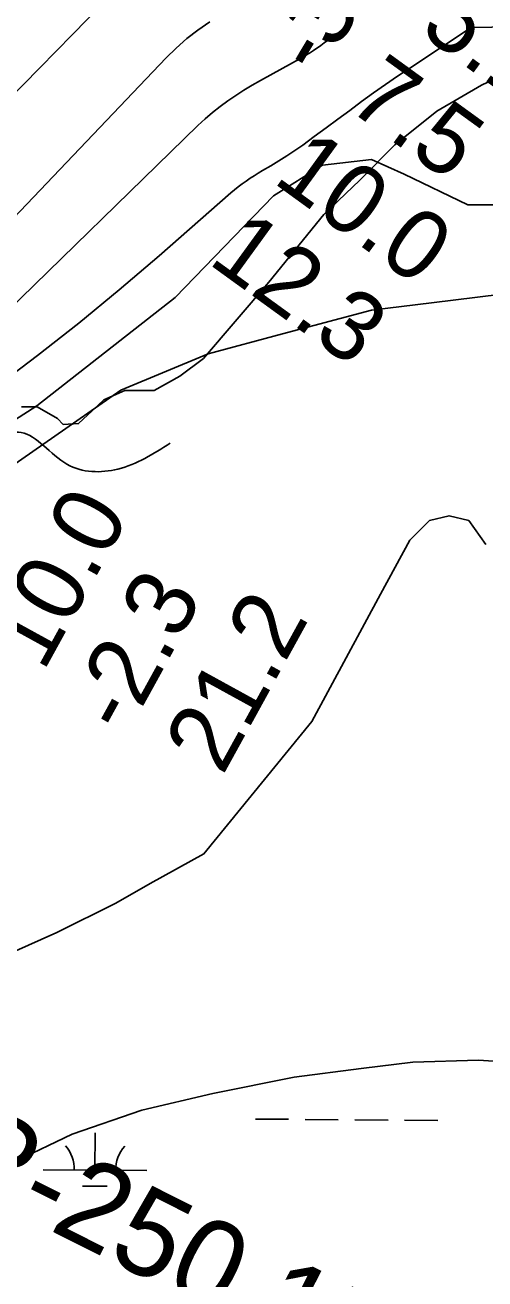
# Model space of a CAD drawing. Extents: x 3271442 to 3309282, y 752266 to 777610.
# Drawn here: x 3291666 to 3292110, y 763821 to 765032 of the extents above; entities that cross this region are included whole.
import ezdxf

# ---------------------------------------------------------------- set-up
doc = ezdxf.new("R2010")
doc.units = 0
for name, color, linetype in [('V-RIVR-EDGE', 7, 'Continuous'), ('V-RIVR-RANG', 7, 'Continuous'), ('V-RIVR-RANG-IDEN', 7, 'Continuous'), ('V-RRAP-FSHR', 7, 'Continuous'), ('V-SITE-VEGE', 7, 'Continuous'), ('V-TOPO-DPTH', 7, 'Continuous'), ('V-TOPO-MINR', 7, 'Continuous'), ('V-TOPO-WATR', 7, 'Continuous'), ('V-WETL-SWMP', 7, 'Continuous')]:
    doc.layers.add(name, color=color, linetype=linetype)

msp = doc.modelspace()

# ---------------------------------------------------------------- linework, layer by layer
at = {"layer": 'V-RIVR-EDGE'}
msp.add_lwpolyline([(3291662.3, 764663.8), (3291677.5, 764663.7), (3291697.1, 764652.4), (3291702.7, 764646.7), (3291717.5, 764647.5), (3291730.5, 764659.7), (3291741.9, 764670.5), (3291762.3, 764679.6), (3291790.6, 764679.5), (3291815.4, 764693.4), (3291838, 764710.3), (3291901.2, 764784), (3291954.4, 764849.5), (3291988.9, 764882.5), (3292022.8, 764916.7), (3292063.4, 764949.2), (3292106.4, 764974.3), (3292150.8, 764995.5)], dxfattribs=at)
at = {"layer": 'V-RRAP-FSHR'}
msp.add_spline([(3289175.3, 762139.2), (3289199.4, 762153.4), (3289238.8, 762167.3), (3289290.8, 762181.4), (3289361.3, 762211.5), (3289422.7, 762245.6), (3289515.6, 762307.8), (3289579.9, 762382.2), (3289624.8, 762451.5), (3289672.3, 762536.1), (3289709.2, 762613.4), (3289742.7, 762696.1), (3289778.2, 762754.9), (3289819.5, 762799.1), (3289911.4, 762921.9), (3289994.1, 763031.2), (3290081.2, 763125.2), (3290188.8, 763225.8), (3290291.4, 763333.1), (3290344.5, 763399.5), (3290388.7, 763467.2), (3290474.1, 763575.3), (3290571, 763693.2), (3290669.8, 763810.1), (3290775.6, 763894), (3290904.1, 763991.9), (3291011.4, 764077.3), (3291099.8, 764130.4), (3291153.6, 764153.5), (3291210.5, 764195.8), (3291300.7, 764249), (3291400.5, 764351.4), (3291483.3, 764483.3), (3291547.7, 764562.3), (3291620.8, 764622.9), (3291662, 764638.8), (3291706.2, 764608.3), (3291755.4, 764603.5), (3291805.9, 764628.5)], degree=3, dxfattribs=at)
at = {"layer": 'V-SITE-VEGE'}
msp.add_lwpolyline([(3290953.5, 763810.1), (3290991.4, 763829), (3291038.7, 763866.9), (3291100.2, 763904.8), (3291199.6, 763956.9), (3291351.1, 764013.7), (3291460, 764061.1), (3291516.8, 764080.1), (3291578.3, 764099), (3291654, 764136.9), (3291696.6, 764155.9), (3291753.4, 764184.3), (3291786.6, 764203.2), (3291838.6, 764231.7), (3291942.8, 764359.6), (3292009, 764482.7), (3292037.4, 764534.8), (3292056.4, 764553.8), (3292075.3, 764558.5), (3292094.2, 764553.8), (3292110.6, 764530.6)], dxfattribs=at)
at = {"layer": 'V-TOPO-DPTH'}
for points in [[(3291487.6, 764670.9), (3291802, 765000.7), (3291811.8, 765010.3), (3291822, 765019.4), (3291832.8, 765027.7), (3291844.1, 765035.5)], [(3291844.1, 765035.5), (3291832.8, 765027.7), (3291822, 765019.4), (3291811.8, 765010.3), (3291802, 765000.7), (3291487.6, 764670.9)], [(3291637.4, 764682.8), (3291677.8, 764713.3), (3291717.8, 764744.4), (3291756.8, 764776.7), (3291795.4, 764809.6), (3291864.5, 764870.3), (3291868.1, 764873.3), (3291871.7, 764876.3), (3291875.5, 764879.1), (3291879.2, 764881.8), (3291883.1, 764884.5), (3291887, 764887), (3291891, 764889.5), (3291895, 764891.9), (3291903, 764896.4), (3291910.9, 764901.2), (3291918.7, 764906.1), (3291926.4, 764911.3), (3291933.9, 764916.6), (3291945.1, 764924.9), (3291956.5, 764933.3), (3291967.9, 764941.7), (3291979.3, 764950.1), (3291990.8, 764958.6), (3292002.2, 764966.9), (3292013.8, 764975.1), (3292025.5, 764983.1), (3292037.2, 764991), (3292096.4, 765030.1), (3292196.8, 765031.7)], [(3291637.4, 764682.8), (3291677.8, 764713.3), (3291717.8, 764744.4), (3291756.8, 764776.7), (3291795.4, 764809.6), (3291864.5, 764870.3), (3291868.1, 764873.3), (3291871.7, 764876.3), (3291875.5, 764879.1), (3291879.2, 764881.8), (3291883.1, 764884.5), (3291887, 764887), (3291891, 764889.5), (3291895, 764891.9), (3291903, 764896.4), (3291910.9, 764901.2), (3291918.7, 764906.1), (3291926.4, 764911.3), (3291933.9, 764916.6), (3291945.1, 764924.9), (3291956.5, 764933.3), (3291967.9, 764941.7), (3291979.3, 764950.1), (3291990.8, 764958.6), (3292002.2, 764966.9), (3292013.8, 764975.1), (3292025.5, 764983.1), (3292037.2, 764991), (3292096.4, 765030.1), (3292196.8, 765031.7)], [(3292170.4, 764778), (3292058.2, 764764), (3292000.3, 764757), (3291914.4, 764734.2), (3291842.5, 764714.9), (3291758.3, 764679.8), (3291652.2, 764605.7)]]:
    msp.add_lwpolyline(points, dxfattribs=at)
at = {"layer": 'V-TOPO-MINR'}
msp.add_line((3291562.9, 764591.7), (3291677.3, 764664.5), dxfattribs=at)
for points in [[(3291648.4, 764958.8), (3291680.1, 764991.1), (3291711.8, 765023.5), (3291781.3, 765095)], [(3291487.6, 764670.9), (3291802, 765000.7), (3291811.8, 765010.3), (3291822, 765019.4), (3291832.8, 765027.7), (3291844.1, 765035.5)], [(3291635.1, 764743), (3291832.8, 764935.5), (3291839.7, 764941.8), (3291846.7, 764948), (3291854.1, 764953.8), (3291861.6, 764959.3), (3291869.3, 764964.6), (3291877.2, 764969.7), (3291885.2, 764974.5), (3291893.3, 764979.1), (3291933.3, 765001.2), (3291937, 765003.3), (3291940.6, 765005.5), (3291944.2, 765007.8), (3291947.7, 765010.3), (3291948.1, 765010.5), (3291951.4, 765012.9), (3291954.7, 765015.3), (3291957.9, 765017.6), (3291961.2, 765020), (3291964.5, 765022.4), (3291967.8, 765024.8), (3291971.1, 765027.1), (3291974.5, 765029.3), (3291979.6, 765032.7)], [(3291677.3, 764664.5), (3291810.9, 764769.3), (3291905.6, 764867.5), (3291953, 764897.3), (3292000.3, 764902.5), (3292031.9, 764888.5), (3292093.3, 764858.7), (3292159.9, 764858.7)], [(3291652.2, 764605.7), (3291758.3, 764679.8), (3291842.5, 764714.9), (3291914.4, 764734.2), (3292000.3, 764757), (3292058.2, 764764), (3292170.4, 764778)]]:
    msp.add_lwpolyline(points, dxfattribs=at)
at = {"layer": 'V-TOPO-WATR'}
msp.add_lwpolyline([(3291637.4, 764682.8), (3291677.8, 764713.3), (3291717.8, 764744.4), (3291756.8, 764776.7), (3291795.4, 764809.6), (3291864.5, 764870.3), (3291868.1, 764873.3), (3291871.7, 764876.3), (3291875.5, 764879.1), (3291879.2, 764881.8), (3291883.1, 764884.5), (3291887, 764887), (3291891, 764889.5), (3291895, 764891.9), (3291903, 764896.4), (3291910.9, 764901.2), (3291918.7, 764906.1), (3291926.4, 764911.3), (3291933.9, 764916.6), (3291945.1, 764924.9), (3291956.5, 764933.3), (3291967.9, 764941.7), (3291979.3, 764950.1), (3291990.8, 764958.6), (3292002.2, 764966.9), (3292013.8, 764975.1), (3292025.5, 764983.1), (3292037.2, 764991), (3292096.4, 765030.1), (3292196.8, 765031.7)], dxfattribs=at)
at = {"layer": 'V-WETL-SWMP'}
for p, q in [((3292040.1, 764030.4), (3292103.6, 764032.6)), ((3292103.6, 764032.6), (3292214.3, 764024.7)), ((3291925.6, 764016), (3291990.3, 764024.4)), ((3291990.3, 764024.4), (3292040.1, 764030.4)), ((3291847.1, 764000.2), (3291925.6, 764016)), ((3291778.6, 763984.3), (3291847.1, 764000.2)), ((3291711.3, 763961), (3291778.6, 763984.3)), ((3291888.3, 763975.6), (3291920.3, 763975.4)), ((3291936.3, 763975.2), (3291968.3, 763975)), ((3291984.3, 763974.8), (3292016.3, 763974.6)), ((3292032.3, 763974.5), (3292064.3, 763974.2)), ((3291657.7, 763935.1), (3291711.3, 763961)), ((3291733.3, 763926.2), (3291733.6, 763962.2)), ((3291683.3, 763926.6), (3291783.3, 763925.8)), ((3291721.2, 763910.8), (3291745.2, 763910.6))]:
    msp.add_line(p, q, dxfattribs=at)
for centre, start, end in [((3291678.1, 763927.1), 358.7563, 40.2999), ((3291788.5, 763926.2), 138.7563, 180.2999)]:
    msp.add_arc(centre, 35.2, start, end, dxfattribs=at)

# ---------------------------------------------------------------- texts
at = {"layer": 'V-RIVR-RANG'}
for s, rotation, p in [('-3', 59.0885, (3291950.3, 764981)), ('5.1', 324.0391, (3292045.1, 765025.8)), ('7.5', 324.0391, (3291974.8, 764953.2)), ('10.0', 324.0391, (3291903.8, 764881.3)), ('12.3', 324.0391, (3291841.2, 764803.1)), ('10.0', 61.2027, (3291683.4, 764406.7)), ('-2.3', 61.2027, (3291763.4, 764344.7)), ('21.2', 61.2027, (3291856.5, 764306.5))]:
    msp.add_text(s, height=67, rotation=rotation, dxfattribs=at).set_placement(p)
at = {"layer": 'V-RIVR-RANG-IDEN'}
msp.add_text('R-250.15', height=83, rotation=333.2614, dxfattribs=at).set_placement((3291583.4, 763921.7))

doc.saveas('drawing.dxf')
